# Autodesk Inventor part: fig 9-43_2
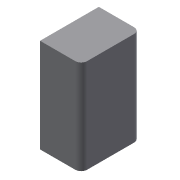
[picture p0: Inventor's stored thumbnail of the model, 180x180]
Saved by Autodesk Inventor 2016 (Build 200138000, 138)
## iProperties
Created: 2013-03
Part Number: fig 9-43_2
Material: Generic
Document SubType Name: Modeling
Designer: CADCIM
Density: 1 g/cm^3
Appearance: Default
Author: CADCIM
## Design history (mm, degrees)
sketch "Sketch1"
  geometry: L1 (-2.508, 1.862)-(2.492, 1.862); L2 (2.492, 1.862)-(2.492, -6.138); L3 (2.492, -6.138)-(-2.508, -6.138); L4 (-2.508, -6.138)-(-2.508, 1.862); 1 further point
  constraints: 8 end point, 2 parallel, 1 horizontal, 1 perpendicular
  dimensions: "d0" = 5 distance of L1.start L1.end; "d2" = 8 distance of L1.end L2.end
extrude "Extrusion1" new body sketch "Sketch1" distance "d3" = 3.5; taper "d4" = 0 deg
fillet "Fillet1" dims "d5" = 0.5
fillet "Fillet2" dims "d6" = 0.5
body "Solid1"
